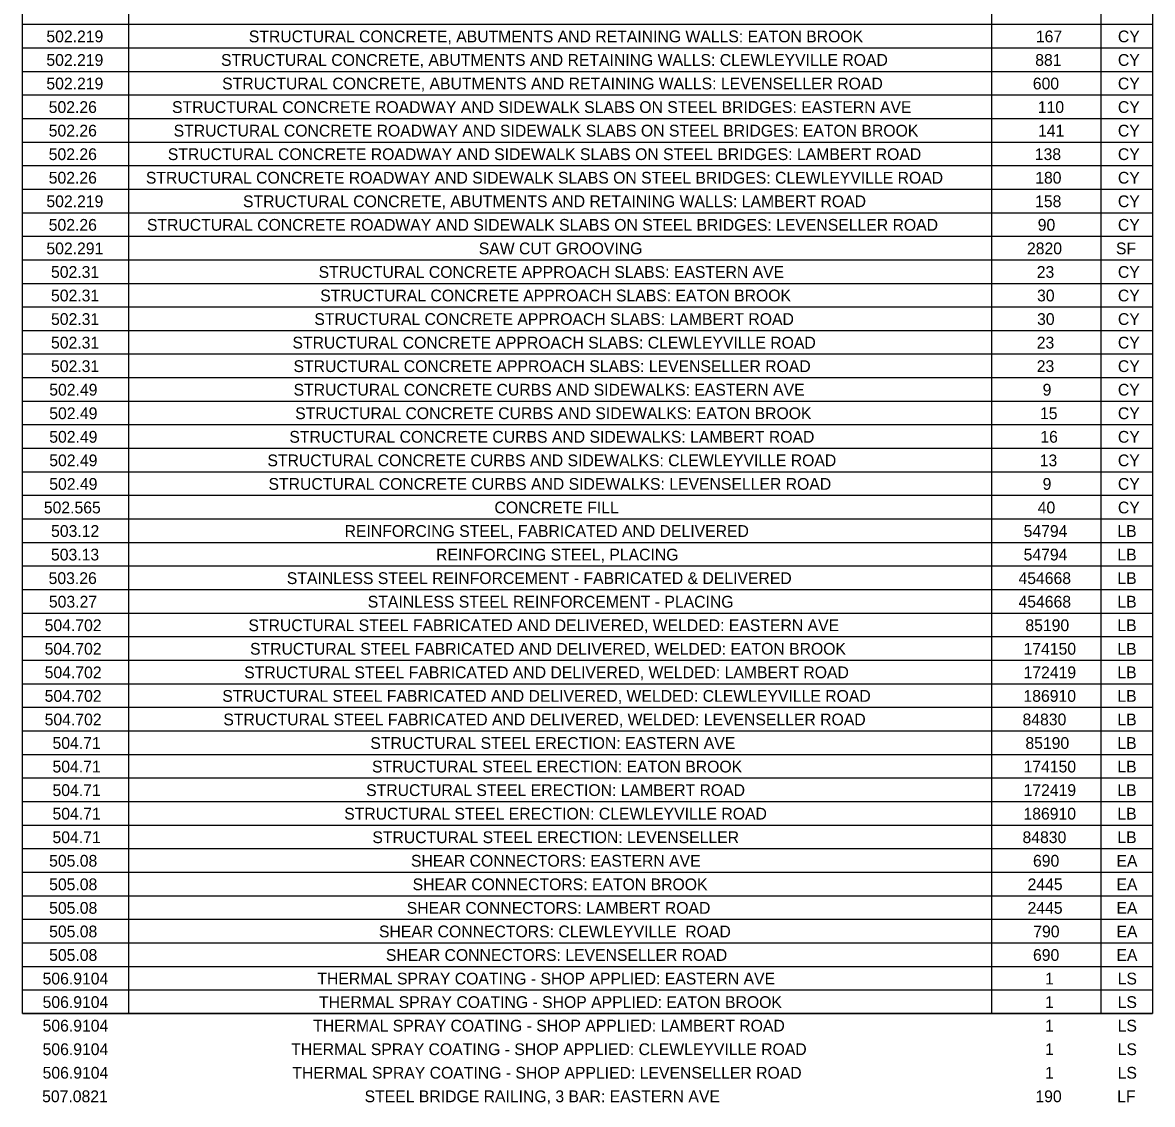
# Model space of a CAD drawing. Extents: x -18.7 to 5.6, y -2.7 to 4.
# Drawn here: x -18.69 to -17.746, y 2.166 to 3.071 of the extents above; entities that cross this region are included whole.
import ezdxf

# ---------------------------------------------------------------- set-up
doc = ezdxf.new("R2010")
doc.units = 0
doc.layers.add('ANNOTATION', color=7, linetype='Continuous')
doc.layers.add('BORDER', color=7, linetype='Continuous')

msp = doc.modelspace()

# ---------------------------------------------------------------- linework, layer by layer
at = {"layer": 'BORDER'}
for p, q in [((-18.60174, 3.9551), (-18.60174, 2.24242)), ((-17.88042, 3.9551), (-17.88042, 2.24242)), ((-17.78903, 3.9551), (-17.78903, 2.24242)), ((-18.69032, 3.06923), (-17.74604, 3.06923)), ((-18.69032, 3.04955), (-17.74604, 3.04955)), ((-18.69032, 3.02986), (-17.74604, 3.02986)), ((-18.69032, 3.01017), (-17.74604, 3.01017)), ((-18.69032, 2.99049), (-17.74604, 2.99049)), ((-18.69032, 2.9708), (-17.74604, 2.9708)), ((-18.69032, 2.95112), (-17.74604, 2.95112)), ((-18.69032, 2.93143), (-17.74604, 2.93143)), ((-18.69032, 2.91174), (-17.74604, 2.91174)), ((-18.69032, 2.89206), (-17.74604, 2.89206)), ((-18.69032, 2.87237), (-17.74604, 2.87237)), ((-18.69032, 2.85269), (-17.74604, 2.85269)), ((-18.69032, 2.833), (-17.74604, 2.833)), ((-18.69032, 2.81331), (-17.74604, 2.81331)), ((-18.69032, 2.79363), (-17.74604, 2.79363)), ((-18.69032, 2.77394), (-17.74604, 2.77394)), ((-18.69032, 2.75426), (-17.74604, 2.75426)), ((-18.69032, 2.73457), (-17.74604, 2.73457)), ((-18.69032, 2.71488), (-17.74604, 2.71488)), ((-18.69032, 2.6952), (-17.74604, 2.6952)), ((-18.69032, 2.67551), (-17.74604, 2.67551)), ((-18.69032, 2.65583), (-17.74604, 2.65583)), ((-18.69032, 2.63614), (-17.74604, 2.63614)), ((-18.69032, 2.61645), (-17.74604, 2.61645)), ((-18.69032, 2.59677), (-17.74604, 2.59677)), ((-18.69032, 2.57708), (-17.74604, 2.57708)), ((-18.69032, 2.5574), (-17.74604, 2.5574)), ((-18.69032, 2.53771), (-17.74604, 2.53771)), ((-18.69032, 2.51802), (-17.74604, 2.51802)), ((-18.69032, 2.49834), (-17.74604, 2.49834)), ((-18.69032, 2.47865), (-17.74604, 2.47865)), ((-18.69032, 2.45897), (-17.74604, 2.45897)), ((-18.69032, 2.43928), (-17.74604, 2.43928)), ((-18.69032, 2.41959), (-17.74604, 2.41959)), ((-18.69032, 2.39991), (-17.74604, 2.39991)), ((-18.69032, 2.38022), (-17.74604, 2.38022)), ((-18.69032, 2.36054), (-17.74604, 2.36054)), ((-18.69032, 2.34085), (-17.74604, 2.34085)), ((-18.69032, 2.32116), (-17.74604, 2.32116)), ((-18.69032, 2.30148), (-17.74604, 2.30148)), ((-18.69032, 2.28179), (-17.74604, 2.28179)), ((-18.69032, 2.26211), (-17.74604, 2.26211)), ((-18.69032, 2.24242), (-17.74604, 2.24242))]:
    msp.add_line(p, q, dxfattribs=at)
msp.add_lwpolyline([(-18.69032, 3.97479), (-17.74604, 3.97479), (-17.74604, 2.24242), (-18.69032, 2.24242)], close=True, dxfattribs=at)

# ---------------------------------------------------------------- texts
at = {"layer": 'ANNOTATION'}
for s, height, p in [('502.219', 0.009843, (-18.67043, 3.05414)), ('STRUCTURAL CONCRETE, ABUTMENTS AND RETAINING WALLS: EATON BROOK', 0.009843, (-18.50123, 3.05414)), ('167', 0.009843, (-17.84343, 3.05414)), ('CY', 0.009843, (-17.77487, 3.05414)), ('502.219', 0.009843, (-18.67043, 3.03446)), ('STRUCTURAL CONCRETE, ABUTMENTS AND RETAINING WALLS: CLEWLEYVILLE ROAD', 0.009843, (-18.52445, 3.03446)), ('881', 0.009843, (-17.84398, 3.03446)), ('CY', 0.009843, (-17.77487, 3.03446)), ('502.219', 0.009843, (-18.67043, 3.01477)), ('STRUCTURAL CONCRETE, ABUTMENTS AND RETAINING WALLS: LEVENSELLER ROAD', 0.009843, (-18.52355, 3.01477)), ('600', 0.009843, (-17.84599, 3.01477)), ('CY', 0.009843, (-17.77487, 3.01477)), ('502.26', 0.009843, (-18.66849, 2.99508)), ('STRUCTURAL CONCRETE ROADWAY AND SIDEWALK SLABS ON STEEL BRIDGES: EASTERN AVE', 0.009843, (-18.56542, 2.99508)), ('110', 0.009843, (-17.84181, 2.99508)), ('CY', 0.009843, (-17.77487, 2.99508)), ('502.26', 0.009843, (-18.66849, 2.9754)), ('STRUCTURAL CONCRETE ROADWAY AND SIDEWALK SLABS ON STEEL BRIDGES: EATON BROOK', 0.009843, (-18.56407, 2.9754)), ('141', 0.009843, (-17.84165, 2.9754)), ('CY', 0.009843, (-17.77487, 2.9754)), ('502.26', 0.009843, (-18.66849, 2.95571)), ('STRUCTURAL CONCRETE ROADWAY AND SIDEWALK SLABS ON STEEL BRIDGES: LAMBERT ROAD', 0.009843, (-18.56896, 2.95571)), ('138', 0.009843, (-17.84432, 2.95571)), ('CY', 0.009843, (-17.77487, 2.95571)), ('502.26', 0.009843, (-18.66849, 2.93603)), ('STRUCTURAL CONCRETE ROADWAY AND SIDEWALK SLABS ON STEEL BRIDGES: CLEWLEYVILLE ROAD', 0.009843, (-18.58728, 2.93603)), ('180', 0.009843, (-17.84398, 2.93603)), ('CY', 0.009843, (-17.77487, 2.93603)), ('502.219', 0.009843, (-18.67043, 2.91634)), ('STRUCTURAL CONCRETE, ABUTMENTS AND RETAINING WALLS: LAMBERT ROAD', 0.009843, (-18.50612, 2.91634)), ('158', 0.009843, (-17.84409, 2.91634)), ('CY', 0.009843, (-17.77487, 2.91634)), ('502.26', 0.009843, (-18.66849, 2.89665)), ('STRUCTURAL CONCRETE ROADWAY AND SIDEWALK SLABS ON STEEL BRIDGES: LEVENSELLER ROAD', 0.009843, (-18.58639, 2.89665)), ('90', 0.009843, (-17.84189, 2.89665)), ('CY', 0.009843, (-17.77487, 2.89665)), ('502.291', 0.009843, (-18.67043, 2.87697)), ('SAW CUT GROOVING', 0.009843, (-18.30904, 2.87697)), ('2820', 0.009843, (-17.85087, 2.87697)), ('SF', 0.009843, (-17.7765, 2.87697)), ('502.31', 0.009843, (-18.66656, 2.85728)), ('STRUCTURAL CONCRETE APPROACH SLABS: EASTERN AVE', 0.009843, (-18.44292, 2.85728)), ('23', 0.009843, (-17.8427, 2.85728)), ('CY', 0.009843, (-17.77487, 2.85728)), ('502.31', 0.009843, (-18.66656, 2.8376)), ('STRUCTURAL CONCRETE APPROACH SLABS: EATON BROOK', 0.009843, (-18.44156, 2.8376)), ('30', 0.009843, (-17.84243, 2.8376)), ('CY', 0.009843, (-17.77487, 2.8376)), ('502.31', 0.009843, (-18.66656, 2.81791)), ('STRUCTURAL CONCRETE APPROACH SLABS: LAMBERT ROAD', 0.009843, (-18.44646, 2.81791)), ('30', 0.009843, (-17.84243, 2.81791)), ('CY', 0.009843, (-17.77487, 2.81791)), ('502.31', 0.009843, (-18.66656, 2.79822)), ('STRUCTURAL CONCRETE APPROACH SLABS: CLEWLEYVILLE ROAD', 0.009843, (-18.46478, 2.79822)), ('23', 0.009843, (-17.8427, 2.79822)), ('CY', 0.009843, (-17.77487, 2.79822)), ('502.31', 0.009843, (-18.66656, 2.77854)), ('STRUCTURAL CONCRETE APPROACH SLABS: LEVENSELLER ROAD', 0.009843, (-18.46388, 2.77854)), ('23', 0.009843, (-17.8427, 2.77854)), ('CY', 0.009843, (-17.77487, 2.77854)), ('502.49', 0.009843, (-18.66803, 2.75885)), ('STRUCTURAL CONCRETE CURBS AND SIDEWALKS: EASTERN AVE', 0.009843, (-18.46383, 2.75885)), ('9', 0.00984, (-17.83778, 2.75885)), ('CY', 0.009843, (-17.77487, 2.75885)), ('502.49', 0.009843, (-18.66803, 2.73917)), ('STRUCTURAL CONCRETE CURBS AND SIDEWALKS: EATON BROOK', 0.009843, (-18.46247, 2.73917)), ('15', 0.009843, (-17.83999, 2.73917)), ('CY', 0.009843, (-17.77487, 2.73917)), ('502.49', 0.009843, (-18.66803, 2.71948)), ('STRUCTURAL CONCRETE CURBS AND SIDEWALKS: LAMBERT ROAD', 0.009843, (-18.46736, 2.71948)), ('16', 0.009843, (-17.83972, 2.71948)), ('CY', 0.009843, (-17.77487, 2.71948)), ('502.49', 0.009843, (-18.66803, 2.69979)), ('STRUCTURAL CONCRETE CURBS AND SIDEWALKS: CLEWLEYVILLE ROAD', 0.009843, (-18.48568, 2.69979)), ('13', 0.009843, (-17.84022, 2.69979)), ('CY', 0.009843, (-17.77487, 2.69979)), ('502.49', 0.009843, (-18.66803, 2.68011)), ('STRUCTURAL CONCRETE CURBS AND SIDEWALKS: LEVENSELLER ROAD', 0.009843, (-18.48479, 2.68011)), ('9', 0.00984, (-17.83778, 2.68011)), ('CY', 0.009843, (-17.77487, 2.68011)), ('502.565', 0.009843, (-18.67256, 2.66042)), ('CONCRETE FILL', 0.009843, (-18.29593, 2.66042)), ('40', 0.009843, (-17.84189, 2.66042)), ('CY', 0.009843, (-17.77487, 2.66042)), ('503.12', 0.009843, (-18.66652, 2.64074)), ('REINFORCING STEEL, FABRICATED AND DELIVERED', 0.009843, (-18.42119, 2.64074)), ('54794', 0.009843, (-17.85366, 2.64074)), ('LB', 0.009843, (-17.7753, 2.64074)), ('503.13', 0.009843, (-18.66659, 2.62105)), ('REINFORCING STEEL, PLACING', 0.009843, (-18.34473, 2.62105)), ('54794', 0.009843, (-17.85366, 2.62105)), ('LB', 0.009843, (-17.7753, 2.62105)), ('503.26', 0.009843, (-18.66857, 2.60136)), ('STAINLESS STEEL REINFORCEMENT - FABRICATED & DELIVERED', 0.009843, (-18.4695, 2.60136)), ('454668', 0.009843, (-17.85796, 2.60136)), ('LB', 0.009843, (-17.7753, 2.60136)), ('503.27', 0.009843, (-18.66834, 2.58168)), ('STAINLESS STEEL REINFORCEMENT - PLACING', 0.009843, (-18.40184, 2.58168)), ('454668', 0.009843, (-17.85796, 2.58168)), ('LB', 0.009843, (-17.7753, 2.58168)), ('504.702', 0.009843, (-18.67187, 2.56199)), ('STRUCTURAL STEEL FABRICATED AND DELIVERED, WELDED: EASTERN AVE', 0.009843, (-18.50157, 2.56199)), ('85190', 0.009843, (-17.85219, 2.56199)), ('LB', 0.009843, (-17.7753, 2.56199)), ('504.702', 0.009843, (-18.67187, 2.54231)), ('STRUCTURAL STEEL FABRICATED AND DELIVERED, WELDED: EATON BROOK', 0.009843, (-18.50021, 2.54231)), ('174150', 0.009843, (-17.85374, 2.54231)), ('LB', 0.009843, (-17.7753, 2.54231)), ('504.702', 0.009843, (-18.67187, 2.52262)), ('STRUCTURAL STEEL FABRICATED AND DELIVERED, WELDED: LAMBERT ROAD', 0.009843, (-18.5051, 2.52262)), ('172419', 0.009843, (-17.85374, 2.52262)), ('LB', 0.009843, (-17.7753, 2.52262)), ('504.702', 0.009843, (-18.67187, 2.50293)), ('STRUCTURAL STEEL FABRICATED AND DELIVERED, WELDED: CLEWLEYVILLE ROAD', 0.009843, (-18.52342, 2.50293)), ('186910', 0.009843, (-17.85381, 2.50293)), ('LB', 0.009843, (-17.7753, 2.50293)), ('504.702', 0.009843, (-18.67187, 2.48325)), ('STRUCTURAL STEEL FABRICATED AND DELIVERED, WELDED: LEVENSELLER ROAD', 0.009843, (-18.52253, 2.48325)), ('84830', 0.009843, (-17.85459, 2.48325)), ('LB', 0.009843, (-17.7753, 2.48325)), ('504.71', 0.009843, (-18.66532, 2.46356)), ('STRUCTURAL STEEL ERECTION: EASTERN AVE', 0.009843, (-18.39965, 2.46356)), ('85190', 0.009843, (-17.85219, 2.46356)), ('LB', 0.009843, (-17.7753, 2.46356)), ('504.71', 0.009843, (-18.66532, 2.44388)), ('STRUCTURAL STEEL ERECTION: EATON BROOK', 0.009843, (-18.39829, 2.44388)), ('174150', 0.009843, (-17.85374, 2.44388)), ('LB', 0.009843, (-17.7753, 2.44388)), ('504.71', 0.009843, (-18.66532, 2.42419)), ('STRUCTURAL STEEL ERECTION: LAMBERT ROAD', 0.009843, (-18.40318, 2.42419)), ('172419', 0.009843, (-17.85374, 2.42419)), ('LB', 0.009843, (-17.7753, 2.42419)), ('504.71', 0.009843, (-18.66532, 2.4045)), ('STRUCTURAL STEEL ERECTION: CLEWLEYVILLE ROAD', 0.009843, (-18.42151, 2.4045)), ('186910', 0.009843, (-17.85381, 2.4045)), ('LB', 0.009843, (-17.7753, 2.4045)), ('504.71', 0.009843, (-18.66532, 2.38482)), ('STRUCTURAL STEEL ERECTION: LEVENSELLER', 0.009843, (-18.39798, 2.38482)), ('84830', 0.009843, (-17.85459, 2.38482)), ('LB', 0.009843, (-17.7753, 2.38482)), ('505.08', 0.009843, (-18.66815, 2.36513)), ('SHEAR CONNECTORS: EASTERN AVE', 0.009843, (-18.36571, 2.36513)), ('690', 0.009843, (-17.84584, 2.36513)), ('EA', 0.009843, (-17.77611, 2.36513)), ('505.08', 0.009843, (-18.66815, 2.34545)), ('SHEAR CONNECTORS: EATON BROOK', 0.009843, (-18.36435, 2.34545)), ('2445', 0.009843, (-17.85037, 2.34545)), ('EA', 0.009843, (-17.77611, 2.34545)), ('505.08', 0.009843, (-18.66815, 2.32576)), ('SHEAR CONNECTORS: LAMBERT ROAD', 0.009843, (-18.36925, 2.32576)), ('2445', 0.009843, (-17.85037, 2.32576)), ('EA', 0.009843, (-17.77611, 2.32576)), ('505.08', 0.009843, (-18.66815, 2.30607)), ('SHEAR CONNECTORS: CLEWLEYVILLE  ROAD', 0.009843, (-18.39245, 2.30607)), ('790', 0.009843, (-17.84561, 2.30607)), ('EA', 0.009843, (-17.77611, 2.30607)), ('505.08', 0.009843, (-18.66815, 2.28639)), ('SHEAR CONNECTORS: LEVENSELLER ROAD', 0.009843, (-18.38667, 2.28639)), ('690', 0.009843, (-17.84584, 2.28639)), ('EA', 0.009843, (-17.77611, 2.28639)), ('506.9104', 0.009843, (-18.6736, 2.2667)), ('THERMAL SPRAY COATING - SHOP APPLIED: EASTERN AVE', 0.009843, (-18.44395, 2.2667)), ('1', 0.00984, (-17.83576, 2.2667)), ('LS', 0.009843, (-17.77506, 2.2667)), ('506.9104', 0.009843, (-18.6736, 2.24702)), ('THERMAL SPRAY COATING - SHOP APPLIED: EATON BROOK', 0.009843, (-18.4426, 2.24702)), ('1', 0.00984, (-17.83576, 2.24702)), ('LS', 0.009843, (-17.77506, 2.24702)), ('506.9104', 0.009843, (-18.6736, 2.22733)), ('THERMAL SPRAY COATING - SHOP APPLIED: LAMBERT ROAD', 0.009843, (-18.44749, 2.22733)), ('1', 0.00984, (-17.83576, 2.22733)), ('LS', 0.009843, (-17.77506, 2.22733)), ('506.9104', 0.009843, (-18.6736, 2.20764)), ('THERMAL SPRAY COATING - SHOP APPLIED: CLEWLEYVILLE ROAD', 0.009843, (-18.46581, 2.20764)), ('1', 0.00984, (-17.83576, 2.20764)), ('LS', 0.009843, (-17.77506, 2.20764)), ('506.9104', 0.009843, (-18.6736, 2.18796)), ('THERMAL SPRAY COATING - SHOP APPLIED: LEVENSELLER ROAD', 0.009843, (-18.46491, 2.18796)), ('1', 0.00984, (-17.83576, 2.18796)), ('LS', 0.009843, (-17.77506, 2.18796)), ('507.0821', 0.009843, (-18.674, 2.16827)), ('STEEL BRIDGE RAILING, 3 BAR: EASTERN AVE', 0.009843, (-18.40447, 2.16827)), ('190', 0.009843, (-17.84382, 2.16827)), ('LF', 0.009843, (-17.77549, 2.16827))]:
    msp.add_text(s, height=height, dxfattribs=at).set_placement(p)

doc.saveas('drawing.dxf')
